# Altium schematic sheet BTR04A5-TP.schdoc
size 127 x 101 mm
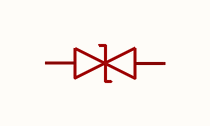
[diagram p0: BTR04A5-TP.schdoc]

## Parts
D?  btr04a5-tp  [D0402-BI]  (value not drawn)

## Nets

Not connected (* = marked no-connect by the designer): D? 1 2

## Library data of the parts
D? = btr04a5-tp: 反向截止电压(Vrwm):5.5V;钳位电压:9V;; Manufacturer: TECH PUBLIC(台舟); AddInBom: yes; ModelId: 62a80a189f1b46df8ba79817b730b378; ModelName: D0402_L1.0-W0.5-H0.5; ModelTransform: 39.37,19.685,0,0,0,0,0,0,0; Reverse Stand-Off Voltage (Vrwm): 5.5V; Clamping Voltage: 9V; Reverse Leakage Current (Ir): 1nA; level of protection: IEC 61000-4-4；IEC 61000-4-5；IEC 61000-4-2; Type: ESD; Junction Capacitance: 5pF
